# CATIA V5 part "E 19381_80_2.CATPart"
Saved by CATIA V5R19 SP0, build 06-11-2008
Definition: E 19381_80_2
Nomenclature: E 19381_80_2
Description: PART-E 19381_80_2-DESC
Material "Plastic": density 1200 kg/m3, Young's modulus 2.2e+09 Pa, Poisson ratio 0.38, thermal expansion 6.84e-05 1/K
Bounding box of the stored display mesh (mm): x 35.5 to 60.5, y -12.5 to 12.5, z -6 to 27.995
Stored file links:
  G:\UTB\Kombinované\Bakalářská práce\Catia\FORMA\E 19381_80_2.CATPart
  D:\Aplikace\CATIA\Nová složka\win_b64\startup\materials\Catalog.CATMaterial
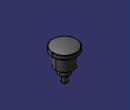
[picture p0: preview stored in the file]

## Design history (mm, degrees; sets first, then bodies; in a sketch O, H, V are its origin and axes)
Body1 "E 19381_80" (main body)
  Solid1: solid without history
